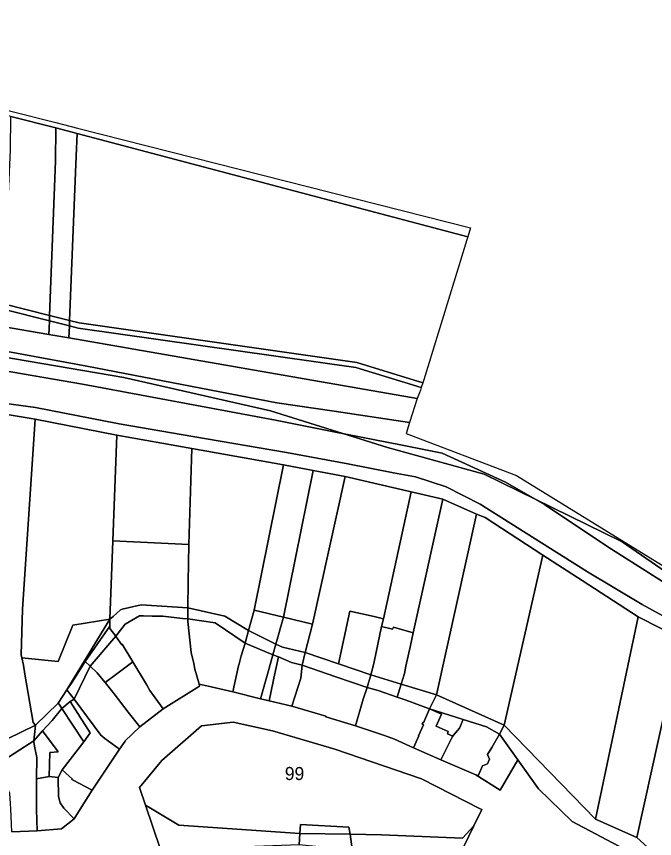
# Model space of a CAD drawing. Extents: x -545779 to -541342, y -1153413 to -1149956.
# Drawn here: x -544310.7 to -544066.7, y -1151065.6 to -1150751.1 of the extents above; entities that cross this region are included whole.
import ezdxf

# ---------------------------------------------------------------- set-up
doc = ezdxf.new("R2010")
doc.units = 0
for name, color, linetype in [('95560013', 7, 'Continuous'), ('95590013', 7, 'Continuous'), ('95610013', 7, 'Continuous'), ('95630013', 7, 'Continuous'), ('95640013', 7, 'Continuous'), ('95660013', 7, 'Continuous')]:
    doc.layers.add(name, color=color, linetype=linetype)

msp = doc.modelspace()

# ---------------------------------------------------------------- linework, layer by layer
at = {"layer": '95560013'}
for points in [[(-544295.7, -1150793.77), (-544295.81, -1150806.53), (-544298.04, -1150865.53), (-544315.7, -1150861.08), (-544312.98, -1150802.25), (-544312.87, -1150789.37)], [(-544287.84, -1150804.52), (-544290.38, -1150867.46), (-544298.04, -1150865.53), (-544295.81, -1150806.53), (-544295.7, -1150793.77), (-544287.44, -1150795.88)], [(-544138.05, -1150835.38), (-544138.43, -1150836.61), (-544154.97, -1150890.12), (-544155.31, -1150891.22), (-544180.51, -1150883.46), (-544286.78, -1150868.37), (-544290.38, -1150867.46), (-544287.84, -1150804.52), (-544287.44, -1150795.88)]]:
    msp.add_lwpolyline(points, close=True, dxfattribs=at)
at = {"layer": '95590013'}
for points in [[(-544303.38, -1151022.3), (-544314.12, -1151027.52), (-544318.86, -1151029.7), (-544323.26, -1150998.27), (-544323.27, -1150993.64), (-544318.24, -1150902.75), (-544303.5, -1150905.18), (-544308.44, -1150977.82), (-544308.88, -1150995.29), (-544308.64, -1150996.44), (-544308.03, -1150999.33), (-544307.45, -1151002.7), (-544304.25, -1151021.22)], [(-544273.79, -1150951.78), (-544275.03, -1150981.73), (-544289.15, -1150984.01), (-544294.75, -1150997.87), (-544308.64, -1150996.44), (-544308.88, -1150995.29), (-544308.44, -1150977.82), (-544303.5, -1150905.18), (-544272.28, -1150911.34)], [(-544244.73, -1150953.19), (-544273.79, -1150951.78), (-544272.28, -1150911.34), (-544243.64, -1150916.44)], [(-544219.85, -1150978.19), (-544221.95, -1150986.09), (-544231.07, -1150980.53), (-544245.1, -1150977.32), (-544245.06, -1150967.45), (-544244.73, -1150953.19), (-544243.64, -1150916.44), (-544208.54, -1150922.71)], [(-544208.54, -1150922.71), (-544197.24, -1150924.84), (-544208.58, -1150980.92), (-544219.85, -1150978.19)], [(-544197.54, -1150983.58), (-544208.58, -1150980.92), (-544197.24, -1150924.84), (-544185.05, -1150927.15)], [(-544173.93, -1150980.64), (-544183.27, -1150978.58), (-544187.57, -1150998.8), (-544200.28, -1150994.43), (-544197.54, -1150983.58), (-544185.05, -1150927.15), (-544159.7, -1150933.01), (-544170.39, -1150981.51)], [(-544171.09, -1150984.55), (-544170.39, -1150981.51), (-544159.7, -1150933.01), (-544147.6, -1150935.85), (-544159.03, -1150986.87), (-544166.56, -1150984.76), (-544166.85, -1150985.46)], [(-544147.6, -1150935.85), (-544134.82, -1150941.49), (-544150.12, -1151010.66), (-544163.6, -1151006.57), (-544162.36, -1151002.54), (-544161.8, -1150999.68), (-544159.99, -1150991.81), (-544159.03, -1150986.87)], [(-544131.46, -1150942.81), (-544109.36, -1150957.22), (-544124.2, -1151022.22), (-544150.12, -1151010.66), (-544134.82, -1150941.49)], [(-544109.36, -1150957.22), (-544094.38, -1150966.9), (-544072.88, -1150980.84), (-544089.31, -1151058.21), (-544124.2, -1151022.22)], [(-544056.62, -1150989.15), (-544073.49, -1151065.25), (-544089.31, -1151058.21), (-544072.88, -1150980.84)], [(-544270.42, -1150991.45), (-544270.24, -1150991.3), (-544266.21, -1150997.98), (-544272.33, -1151002.64), (-544276.73, -1151005.94), (-544277.57, -1151005.06), (-544279.78, -1151002.2), (-544282.57, -1150999.63), (-544272.71, -1150988.21), (-544272.56, -1150988.4)]]:
    msp.add_lwpolyline(points, close=True, dxfattribs=at)
at = {"layer": '95610013'}
msp.add_lwpolyline([(-544046.53, -1150994.27), (-544062.75, -1151069.21), (-544063.79, -1151074.07), (-544073.49, -1151065.25), (-544056.62, -1150989.15)], close=True, dxfattribs=at)
at = {"layer": '95630013'}
for points in [[(-544497.37, -1150896.16), (-544458.9, -1150891.75), (-544371.84, -1150878.72), (-544341.86, -1150876.04), (-544317.11, -1150878.83), (-544283.77, -1150884.86), (-544211.12, -1150898.96), (-544189.25, -1150902.17), (-544160.33, -1150906.42), (-544161.7, -1150910.69), (-544119.43, -1150926.78), (-544052.4, -1150968.07)], [(-544062.24, -1150968.12), (-544084.54, -1150954.05), (-544108.79, -1150937.82), (-544123.65, -1150929.34), (-544147.92, -1150918.16), (-544163.14, -1150915.17), (-544189.92, -1150909.92), (-544211.6, -1150905.59), (-544285.48, -1150891.85), (-544319.63, -1150885.97), (-544342.07, -1150883.41), (-544370.99, -1150885.95), (-544459.64, -1150898.72), (-544497.41, -1150904.1)]]:
    msp.add_lwpolyline(points, dxfattribs=at)
for points in [[(-544183.14, -1151063.96), (-544183.56, -1151061.21), (-544202.03, -1151060.27), (-544202.28, -1151063.65), (-544248.55, -1151060.53), (-544261.39, -1151052.79), (-544263.64, -1151046.09), (-544255.06, -1151035.76), (-544239.88, -1151022.55), (-544227.79, -1151021.07), (-544212.83, -1151024.4), (-544188.98, -1151031.43), (-544155.85, -1151042.75), (-544133.31, -1151054.25), (-544132.77, -1151054.51), (-544135.83, -1151060.82), (-544140.09, -1151065.42), (-544171.16, -1151064.15)], [(-544183.14, -1151063.96), (-544202.28, -1151063.65), (-544202.03, -1151060.27), (-544183.56, -1151061.21)]]:
    msp.add_lwpolyline(points, close=True, dxfattribs=at)
at = {"layer": '95640013'}
for points in [[(-544295.68, -1150791.73), (-544287.35, -1150793.85), (-544137.02, -1150832.04), (-544138.05, -1150835.38), (-544287.44, -1150795.88), (-544295.7, -1150793.77), (-544312.87, -1150789.37), (-544393.25, -1150768.78), (-544394.06, -1150768.61), (-544398.19, -1150767.72), (-544398.06, -1150765.72), (-544394, -1150766.75), (-544312.85, -1150787.37)], [(-544338.91, -1150855.23), (-544315.7, -1150861.08), (-544298.04, -1150865.53), (-544298.06, -1150866.03), (-544298.1, -1150867.08), (-544298.12, -1150867.58), (-544315.79, -1150863.12), (-544339.08, -1150857.24), (-544389.1, -1150860.97), (-544398.09, -1150862.89), (-544441.01, -1150872.08), (-544451.94, -1150874.42), (-544453.08, -1150876.18), (-544454.93, -1150879.06), (-544455.39, -1150879.13), (-544457.14, -1150879.42), (-544457.6, -1150879.49), (-544455.47, -1150876.18), (-544453.18, -1150872.64), (-544440.91, -1150870.01), (-544397.99, -1150860.82), (-544389.37, -1150858.98)], [(-544316.1, -1150869.68), (-544315.96, -1150866.8), (-544315.79, -1150863.12), (-544298.12, -1150867.58), (-544298.23, -1150870.34), (-544298.31, -1150872.77)], [(-544298.04, -1150865.53), (-544290.38, -1150867.46), (-544290.4, -1150867.97), (-544290.44, -1150869), (-544290.46, -1150869.51), (-544298.12, -1150867.58), (-544298.1, -1150867.08), (-544298.06, -1150866.03)], [(-544180.51, -1150883.46), (-544155.31, -1150891.22), (-544155.87, -1150893.02), (-544180.94, -1150885.41), (-544287.16, -1150870.34), (-544290.46, -1150869.51), (-544290.44, -1150869), (-544290.4, -1150867.97), (-544290.38, -1150867.46), (-544286.78, -1150868.37)], [(-544298.23, -1150870.34), (-544298.12, -1150867.58), (-544290.46, -1150869.51), (-544290.56, -1150871.9), (-544290.65, -1150874.11), (-544298.31, -1150872.77)], [(-544156.18, -1150894.03), (-544156.62, -1150895.12), (-544156.98, -1150896.02), (-544157.4, -1150897.33), (-544290.65, -1150874.11), (-544290.56, -1150871.9), (-544290.46, -1150869.51), (-544287.16, -1150870.34), (-544180.94, -1150885.41), (-544155.87, -1150893.02)], [(-544245.06, -1150967.45), (-544245.1, -1150977.32), (-544263.03, -1150976.23), (-544270.33, -1150977.91), (-544270.88, -1150978.1), (-544273.69, -1150980.68), (-544275.03, -1150981.73), (-544273.79, -1150951.78), (-544244.73, -1150953.19)], [(-544270.88, -1150978.1), (-544270.33, -1150977.91), (-544263.03, -1150976.23), (-544245.1, -1150977.32), (-544245.11, -1150981.62), (-544247.14, -1150981.39), (-544254.68, -1150980.52), (-544258.85, -1150980.49), (-544262.18, -1150980.47), (-544263.61, -1150980.46), (-544269.16, -1150983.58), (-544272.71, -1150988.21), (-544275.04, -1150985.27), (-544275.04, -1150984.37), (-544275.03, -1150981.73), (-544273.69, -1150980.68)], [(-544231.07, -1150980.53), (-544221.95, -1150986.09), (-544223.24, -1150990.93), (-544234.67, -1150983.13), (-544245.11, -1150981.62), (-544245.1, -1150977.32)], [(-544269.16, -1150983.58), (-544263.61, -1150980.46), (-544262.18, -1150980.47), (-544258.85, -1150980.49), (-544254.68, -1150980.52), (-544247.14, -1150981.39), (-544245.11, -1150981.62), (-544245.18, -1150982.58), (-544243.87, -1150994.4), (-544242.9, -1150998.66), (-544242.43, -1151000.76), (-544240.97, -1151005.99), (-544240.8, -1151006.59), (-544240.68, -1151007.33), (-544254.64, -1151016.06), (-544259.71, -1151009.04), (-544260.97, -1151006.66), (-544266.21, -1150997.98), (-544270.24, -1150991.3), (-544270.42, -1150991.45), (-544272.56, -1150988.4), (-544272.71, -1150988.21)], [(-544211.47, -1150991.25), (-544221.95, -1150986.09), (-544219.85, -1150978.19), (-544208.58, -1150980.92)], [(-544174.4, -1151000.16), (-544175.2, -1151003.05), (-544187.57, -1150998.8), (-544183.27, -1150978.58), (-544173.93, -1150980.64), (-544170.39, -1150981.51), (-544171.09, -1150984.55), (-544173.92, -1150997.98)], [(-544275.03, -1150981.73), (-544291.42, -1151008.67), (-544294.69, -1151013.82), (-544303.38, -1151022.3), (-544304.25, -1151021.22), (-544307.45, -1151002.7), (-544308.03, -1150999.33), (-544308.64, -1150996.44), (-544294.75, -1150997.87), (-544289.15, -1150984.01)], [(-544275.03, -1150981.73), (-544275.04, -1150984.37), (-544284.4, -1150997.93), (-544289.39, -1151005.78), (-544291.42, -1151008.67)], [(-544245.18, -1150982.58), (-544245.11, -1150981.62), (-544234.67, -1150983.13), (-544223.24, -1150990.93), (-544224.74, -1150995.76), (-544225.56, -1150998.83), (-544225.75, -1150999.54), (-544227.99, -1151009.48), (-544236.21, -1151007.63), (-544240.8, -1151006.59), (-544240.97, -1151005.99), (-544242.43, -1151000.76), (-544242.9, -1150998.66), (-544243.87, -1150994.4)], [(-544200.28, -1150994.43), (-544209.02, -1150992.45), (-544211.47, -1150991.25), (-544208.58, -1150980.92), (-544197.54, -1150983.58)], [(-544284.4, -1150997.93), (-544275.04, -1150984.37), (-544275.04, -1150985.27), (-544272.71, -1150988.21), (-544282.57, -1150999.63)], [(-544223.24, -1150990.93), (-544221.95, -1150986.09), (-544211.47, -1150991.25), (-544212.6, -1150995.3)], [(-544159.03, -1150986.87), (-544159.99, -1150991.81), (-544161.8, -1150999.68), (-544162.36, -1151002.54), (-544163.6, -1151006.57), (-544175.2, -1151003.05), (-544174.4, -1151000.16), (-544173.92, -1150997.98), (-544171.09, -1150984.55), (-544166.85, -1150985.46), (-544166.56, -1150984.76)], [(-544225.56, -1150998.83), (-544224.74, -1150995.76), (-544223.24, -1150990.93), (-544212.6, -1150995.3), (-544214.44, -1151001.88), (-544217.31, -1151012.11), (-544227.99, -1151009.48), (-544225.75, -1150999.54)], [(-544209.02, -1150992.45), (-544200.28, -1150994.43), (-544201.5, -1150999.28), (-544205.48, -1150998.23), (-544210.54, -1150996.15), (-544212.6, -1150995.3), (-544211.47, -1150991.25)], [(-544212.27, -1151004.25), (-544212.53, -1151005.48), (-544214.12, -1151012.89), (-544217.31, -1151012.11), (-544214.44, -1151001.88), (-544212.6, -1150995.3), (-544210.54, -1150996.15)], [(-544214.12, -1151012.89), (-544212.53, -1151005.48), (-544212.27, -1151004.25), (-544210.54, -1150996.15), (-544205.48, -1150998.23), (-544201.5, -1150999.28), (-544201.94, -1151004.32), (-544205.37, -1151014.99)], [(-544201.5, -1150999.28), (-544200.28, -1150994.43), (-544187.57, -1150998.8), (-544175.2, -1151003.05), (-544176.54, -1151007.87), (-544188.61, -1151003.71)], [(-544288.63, -1151012.25), (-544291.42, -1151008.67), (-544289.39, -1151005.78), (-544284.4, -1150997.93), (-544282.57, -1150999.63)], [(-544277.57, -1151005.06), (-544276.73, -1151005.94), (-544273.37, -1151010.31), (-544268.01, -1151017.23), (-544263.54, -1151022.86), (-544269.25, -1151028.35), (-544269.15, -1151028.43), (-544271.34, -1151031.38), (-544276.85, -1151027.35), (-544278.46, -1151026.1), (-544288.63, -1151012.25), (-544282.57, -1150999.63), (-544279.78, -1151002.2)], [(-544254.64, -1151016.06), (-544263.54, -1151022.86), (-544268.01, -1151017.23), (-544273.37, -1151010.31), (-544276.73, -1151005.94), (-544272.33, -1151002.64), (-544266.21, -1150997.98), (-544260.97, -1151006.66), (-544259.71, -1151009.04)], [(-544201.5, -1150999.28), (-544188.61, -1151003.71), (-544176.54, -1151007.87), (-544178.1, -1151012.34), (-544181.06, -1151022.45), (-544192.4, -1151019.04), (-544192.34, -1151018.83), (-544205.37, -1151014.99), (-544201.94, -1151004.32)], [(-544165.12, -1151011.5), (-544172.34, -1151009.04), (-544176.54, -1151007.87), (-544175.2, -1151003.05), (-544163.6, -1151006.57)], [(-544294.69, -1151013.82), (-544291.42, -1151008.67), (-544288.63, -1151012.25), (-544290.19, -1151013.19), (-544293.35, -1151015.9), (-544294.16, -1151014.63)], [(-544152.75, -1151016.04), (-544155.09, -1151021.33), (-544155.33, -1151021.23), (-544155.6, -1151021.88), (-544155.09, -1151022.11), (-544156.98, -1151026.31), (-544156.85, -1151026.39), (-544158.87, -1151030.91), (-544166.12, -1151027.56), (-544169.93, -1151026.19), (-544181.06, -1151022.45), (-544178.1, -1151012.34), (-544176.54, -1151007.87), (-544172.34, -1151009.04), (-544165.12, -1151011.5), (-544162.08, -1151012.58)], [(-544162.08, -1151012.58), (-544165.12, -1151011.5), (-544163.6, -1151006.57), (-544150.12, -1151010.66), (-544152.75, -1151016.04)], [(-544126.02, -1151025.74), (-544130.92, -1151022.83), (-544139.87, -1151020.05), (-544152.75, -1151016.04), (-544150.12, -1151010.66), (-544124.2, -1151022.22)], [(-544303.38, -1151022.3), (-544294.69, -1151013.82), (-544294.16, -1151014.63), (-544293.35, -1151015.9), (-544297.08, -1151020.51), (-544300.72, -1151024.41), (-544304.06, -1151028.26)], [(-544282.56, -1151025.13), (-544284.88, -1151028.63), (-544293.35, -1151015.9), (-544290.19, -1151013.19)], [(-544288.63, -1151012.25), (-544278.46, -1151026.1), (-544276.85, -1151027.35), (-544271.34, -1151031.38), (-544281.81, -1151047.05), (-544289.24, -1151043.14), (-544289.55, -1151042.97), (-544289.39, -1151042.72), (-544290.51, -1151041.72), (-544293.28, -1151039.38), (-544284.88, -1151028.63), (-544282.56, -1151025.13), (-544290.19, -1151013.19)], [(-544293.28, -1151039.38), (-544294.75, -1151042.29), (-544298.14, -1151041.85), (-544297.93, -1151032.72), (-544294.72, -1151032.48), (-544300.72, -1151024.41), (-544297.08, -1151020.51), (-544293.35, -1151015.9), (-544284.88, -1151028.63)], [(-544155.33, -1151021.23), (-544155.09, -1151021.33), (-544152.75, -1151016.04), (-544148.09, -1151018.03), (-544150.18, -1151022.58), (-544145.65, -1151024.7), (-544145.89, -1151025.59), (-544143.86, -1151026.48), (-544144.28, -1151027.39), (-544148.39, -1151035.46), (-544158.87, -1151030.91), (-544156.85, -1151026.39), (-544156.98, -1151026.31), (-544155.09, -1151022.11), (-544155.6, -1151021.88)], [(-544139.87, -1151020.05), (-544141.23, -1151023.42), (-544143.56, -1151026.13), (-544143.86, -1151026.48), (-544145.89, -1151025.59), (-544145.65, -1151024.7), (-544150.18, -1151022.58), (-544148.09, -1151018.03), (-544152.75, -1151016.04)], [(-544130.56, -1151037.04), (-544132.43, -1151037.76), (-544134.13, -1151041.69), (-544135.01, -1151041.31), (-544148.39, -1151035.46), (-544144.28, -1151027.39), (-544143.86, -1151026.48), (-544143.56, -1151026.13), (-544141.23, -1151023.42), (-544139.87, -1151020.05), (-544130.92, -1151022.83), (-544126.02, -1151025.74), (-544128.94, -1151030.78), (-544130.55, -1151033.44), (-544129.76, -1151035.27)], [(-544317.11, -1151036.5), (-544318.86, -1151029.7), (-544314.12, -1151027.52), (-544303.38, -1151022.3), (-544304.06, -1151028.26)], [(-544302.9, -1151034.58), (-544303.77, -1151030.34), (-544304.11, -1151028.68), (-544304.06, -1151028.26), (-544300.72, -1151024.41), (-544294.72, -1151032.48), (-544297.93, -1151032.72), (-544298.14, -1151041.85), (-544303.07, -1151042.8)], [(-544098.17, -1151059.13), (-544111.06, -1151046.56), (-544118.97, -1151035.55), (-544126.02, -1151025.74), (-544124.2, -1151022.22), (-544089.31, -1151058.21), (-544073.49, -1151065.25), (-544063.79, -1151074.07), (-544054.09, -1151079.29), (-544036.94, -1151082.63), (-544035.48, -1151082.92), (-544037.04, -1151089.82), (-544038.51, -1151089.36), (-544046.4, -1151086.9), (-544054.67, -1151082.43), (-544078.21, -1151069.72)], [(-544128.94, -1151030.78), (-544126.02, -1151025.74), (-544118.97, -1151035.55), (-544125.68, -1151047.13), (-544135.01, -1151041.31), (-544134.13, -1151041.69), (-544132.43, -1151037.76), (-544130.56, -1151037.04), (-544129.76, -1151035.27), (-544130.55, -1151033.44)], [(-544303.77, -1151030.34), (-544302.9, -1151034.58), (-544303.07, -1151042.8), (-544302.99, -1151054.57), (-544302.75, -1151062.65), (-544312.53, -1151063.09), (-544312.84, -1151054.25), (-544312.98, -1151052.2), (-544313.24, -1151048.34), (-544314.29, -1151045.96), (-544315.13, -1151043.69), (-544316.92, -1151037.05), (-544317.11, -1151036.5), (-544304.06, -1151028.26), (-544304.11, -1151028.68)], [(-544281.81, -1151047.05), (-544286.37, -1151054.32), (-544288.69, -1151058.11), (-544292.64, -1151054.05), (-544294.01, -1151051.9), (-544294.57, -1151049.49), (-544294.75, -1151042.29), (-544293.28, -1151039.38), (-544290.51, -1151041.72), (-544289.39, -1151042.72), (-544289.55, -1151042.97), (-544289.24, -1151043.14)], [(-544288.69, -1151058.11), (-544293.42, -1151061.86), (-544302.75, -1151062.65), (-544302.99, -1151054.57), (-544303.07, -1151042.8), (-544298.14, -1151041.85), (-544294.75, -1151042.29), (-544294.57, -1151049.49), (-544294.01, -1151051.9), (-544292.64, -1151054.05)], [(-544202.6, -1151068.01), (-544226.12, -1151068.98), (-544244.82, -1151069.16), (-544255.79, -1151069.46), (-544261.39, -1151052.79), (-544248.55, -1151060.53), (-544202.28, -1151063.65)], [(-544171.16, -1151064.15), (-544140.09, -1151065.42), (-544135.83, -1151060.82), (-544141.57, -1151072.66), (-544147.35, -1151072.15), (-544170.42, -1151070.01), (-544182.27, -1151069.63), (-544183.14, -1151063.96)], [(-544183.14, -1151063.96), (-544182.27, -1151069.63), (-544188.57, -1151069.43), (-544202.6, -1151068.01), (-544202.28, -1151063.65)]]:
    msp.add_lwpolyline(points, close=True, dxfattribs=at)
for points in [[(-544503.41, -1150886.87), (-544457.6, -1150879.49), (-544457.14, -1150879.42), (-544455.39, -1150879.13), (-544454.93, -1150879.06), (-544441.24, -1150876.85), (-544398.42, -1150869.95), (-544373.58, -1150865.95), (-544344.25, -1150864.77), (-544316.1, -1150869.68), (-544298.31, -1150872.77), (-544290.65, -1150874.11), (-544157.4, -1150897.33), (-544160.33, -1150906.42), (-544189.25, -1150902.17), (-544211.12, -1150898.96), (-544283.77, -1150884.86), (-544317.11, -1150878.83), (-544341.86, -1150876.04), (-544371.84, -1150878.72), (-544458.9, -1150891.75), (-544497.37, -1150896.16)], [(-544497.41, -1150904.1), (-544459.64, -1150898.72), (-544370.99, -1150885.95), (-544342.07, -1150883.41), (-544319.63, -1150885.97), (-544285.48, -1150891.85), (-544211.6, -1150905.59), (-544189.92, -1150909.92), (-544163.14, -1150915.17), (-544147.92, -1150918.16), (-544123.65, -1150929.34), (-544108.79, -1150937.82), (-544084.54, -1150954.05), (-544062.24, -1150968.12)], [(-544055.56, -1150984.77), (-544071.41, -1150976.11), (-544092.35, -1150963.53), (-544133.39, -1150937.74), (-544146.34, -1150931.13), (-544158.14, -1150927.27), (-544166.52, -1150925.65), (-544183.95, -1150922.29), (-544207.45, -1150917.93), (-544243.2, -1150911.81), (-544271.36, -1150907), (-544303.43, -1150900.67), (-544317.51, -1150898.82), (-544331.01, -1150896.39), (-544333.16, -1150896.18), (-544341.39, -1150895.37), (-544356.47, -1150896.82), (-544376.63, -1150898.77), (-544443.91, -1150908.54), (-544465.66, -1150911.27), (-544480.24, -1150912.9), (-544495.32, -1150914.58)], [(-544317.51, -1150898.82), (-544303.43, -1150900.67), (-544271.36, -1150907), (-544243.2, -1150911.81), (-544207.45, -1150917.93), (-544183.95, -1150922.29), (-544166.52, -1150925.65), (-544158.14, -1150927.27), (-544146.34, -1150931.13), (-544133.39, -1150937.74), (-544092.35, -1150963.53), (-544071.41, -1150976.11), (-544055.56, -1150984.77)], [(-544056.62, -1150989.15), (-544072.88, -1150980.84), (-544094.38, -1150966.9), (-544109.36, -1150957.22), (-544131.46, -1150942.81), (-544134.82, -1150941.49), (-544147.6, -1150935.85), (-544159.7, -1150933.01), (-544185.05, -1150927.15), (-544197.24, -1150924.84), (-544208.54, -1150922.71), (-544243.64, -1150916.44), (-544272.28, -1150911.34), (-544303.5, -1150905.18), (-544318.24, -1150902.75)], [(-544312.53, -1151063.09), (-544302.75, -1151062.65), (-544293.42, -1151061.86), (-544288.69, -1151058.11), (-544286.37, -1151054.32), (-544281.81, -1151047.05), (-544271.34, -1151031.38), (-544269.15, -1151028.43), (-544269.25, -1151028.35), (-544263.54, -1151022.86), (-544254.64, -1151016.06), (-544240.68, -1151007.33), (-544240.8, -1151006.59), (-544236.21, -1151007.63), (-544227.99, -1151009.48), (-544217.31, -1151012.11), (-544214.12, -1151012.89), (-544205.37, -1151014.99), (-544192.34, -1151018.83), (-544192.4, -1151019.04), (-544181.06, -1151022.45), (-544169.93, -1151026.19), (-544166.12, -1151027.56), (-544158.87, -1151030.91), (-544148.39, -1151035.46), (-544135.01, -1151041.31), (-544125.68, -1151047.13), (-544118.97, -1151035.55), (-544111.06, -1151046.56), (-544098.17, -1151059.13), (-544078.21, -1151069.72)], [(-544141.57, -1151072.66), (-544135.83, -1151060.82), (-544132.77, -1151054.51), (-544133.31, -1151054.25), (-544155.85, -1151042.75), (-544188.98, -1151031.43), (-544212.83, -1151024.4), (-544227.79, -1151021.07), (-544239.88, -1151022.55), (-544255.06, -1151035.76), (-544263.64, -1151046.09), (-544261.39, -1151052.79), (-544255.79, -1151069.46)]]:
    msp.add_lwpolyline(points, dxfattribs=at)
at = {"layer": '95660013'}
for points in [[(-544392.22, -1150674.11), (-544397.72, -1150760.42), (-544397.85, -1150762.48), (-544398.04, -1150765.38), (-544398.06, -1150765.72), (-544394, -1150766.75), (-544312.85, -1150787.37), (-544295.68, -1150791.73), (-544287.35, -1150793.85), (-544137.02, -1150832.04), (-544138.05, -1150835.38), (-544138.43, -1150836.61), (-544154.97, -1150890.12), (-544155.31, -1150891.22), (-544155.87, -1150893.02), (-544156.18, -1150894.03), (-544156.62, -1150895.12), (-544156.98, -1150896.02), (-544157.4, -1150897.33), (-544160.33, -1150906.42), (-544161.7, -1150910.69), (-544119.43, -1150926.78), (-544052.4, -1150968.07)], [(-544490.395, -1150902.035), (-544425.322, -1150891.827), (-544381.939, -1150882.895), (-544356.419, -1150879.067), (-544321.969, -1150880.343), (-544269.653, -1150889.275), (-544213.511, -1150902.035), (-544168.853, -1150916.07), (-544131.849, -1150926.278), (-544079.535, -1150951.797), (-544079.025, -1150952.149), (-544042.531, -1150977.317)], [(-544042.531, -1150977.317), (-544079.025, -1150952.149), (-544079.535, -1150951.797), (-544131.849, -1150926.278), (-544168.853, -1150916.07), (-544213.511, -1150902.035), (-544269.653, -1150889.275), (-544321.969, -1150880.343), (-544356.419, -1150879.067), (-544381.939, -1150882.895), (-544425.322, -1150891.827), (-544490.395, -1150902.035)]]:
    msp.add_lwpolyline(points, dxfattribs=at)
for points in [[(-544132.77, -1151054.51), (-544133.31, -1151054.25), (-544155.85, -1151042.75), (-544188.98, -1151031.43), (-544212.83, -1151024.4), (-544227.79, -1151021.07), (-544239.88, -1151022.55), (-544255.06, -1151035.76), (-544263.64, -1151046.09), (-544261.39, -1151052.79), (-544248.55, -1151060.53), (-544202.28, -1151063.65), (-544183.14, -1151063.96), (-544171.16, -1151064.15), (-544140.09, -1151065.42), (-544135.83, -1151060.82)], [(-544133.31, -1151054.25), (-544132.77, -1151054.51), (-544135.83, -1151060.82), (-544140.09, -1151065.42), (-544171.16, -1151064.15), (-544183.14, -1151063.96), (-544202.28, -1151063.65), (-544248.55, -1151060.53), (-544261.39, -1151052.79), (-544263.64, -1151046.09), (-544255.06, -1151035.76), (-544239.88, -1151022.55), (-544227.79, -1151021.07), (-544212.83, -1151024.4), (-544188.98, -1151031.43), (-544155.85, -1151042.75)]]:
    msp.add_lwpolyline(points, close=True, dxfattribs=at)

# ---------------------------------------------------------------- texts
msp.add_text('99', height=5, rotation=0, dxfattribs=at).set_placement((-544208.078, -1151043.245))

doc.saveas('drawing.dxf')
